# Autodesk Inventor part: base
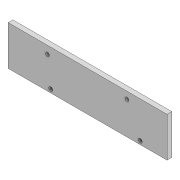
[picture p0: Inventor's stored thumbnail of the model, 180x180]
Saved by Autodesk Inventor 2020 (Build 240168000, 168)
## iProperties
Created: 2019-12
Part Number: base
Material: Generic
Document SubType Name: Modeling
Designer: Dell
Density: 1 g/cm^3
Appearance: Default
Author: Dell
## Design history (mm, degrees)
sketch "Sketch1"
  geometry: L1 (0, 0)-(200, 0); L2 (200, 0)-(200, 50); L3 (200, 50)-(0, 50); L4 (0, 50)-(0, 0); L5 (0, 4.407)-(53.64, 4.407); C1 r 2.5 at (53.64, 4.407)
  constraints: 10 end point, 2 horizontal, 2 parallel, 1 centre point, 1 coincident, 1 perpendicular, 1 point on line
  dimensions: "d0" = 200 distance of L3.end L2.end; "d1" = 50 distance of L2.end L1.end; "d2" = 53.64 distance of L5.start L5.end; "d3" = 5 diameter of C1
extrude "Extrusion1" new body sketch "Sketch1" distance "d4" = 6; taper "d5" = 0 deg
sketch "Sketch2"
  geometry: L1 (53.64, 4.407)-(200, 4.407); L2 (200, 0)-(200, 50) reference; L3 (200, 4.407)-(166.29, 4.407); C1 r 2.5 at (53.64, 4.407) reference; C2 r 2.5 at (166.29, 4.407); 1 further point
  constraints: 4 end point, 2 point on line, 1 centre point, 1 coincident, 1 horizontal
  dimensions: "d6" = 33.71 distance of L1.end L3.end; "d7" = 5 diameter of C2
extrude "Extrusion2" cut sketch "Sketch2" distance "d8" = 6; taper "d9" = 0 deg
sketch "Sketch3"
  geometry: L1 (0, 50)-(0, 0) reference; L2 (0, 40.051)-(49.498, 40.051); C1 r 2.5 at (49.498, 40.051)
  constraints: 2 end point, 1 centre point, 1 coincident, 1 horizontal, 1 point on line
  dimensions: "d10" = 5 diameter of C1
extrude "Extrusion3" cut sketch "Sketch3" distance "d11" = 6; taper "d12" = 0 deg
sketch "Sketch4"
  geometry: L1 (200, 0)-(200, 50) reference; L2 (200, 41.115)-(149.559, 41.115); C1 r 2.5 at (149.559, 41.115); 1 further point
  constraints: 2 end point, 1 centre point, 1 coincident, 1 horizontal, 1 point on line
  dimensions: "d13" = 5 diameter of C1
extrude "Extrusion4" cut sketch "Sketch4" distance "d14" = 6; taper "d15" = 0 deg
body "Solid1"
